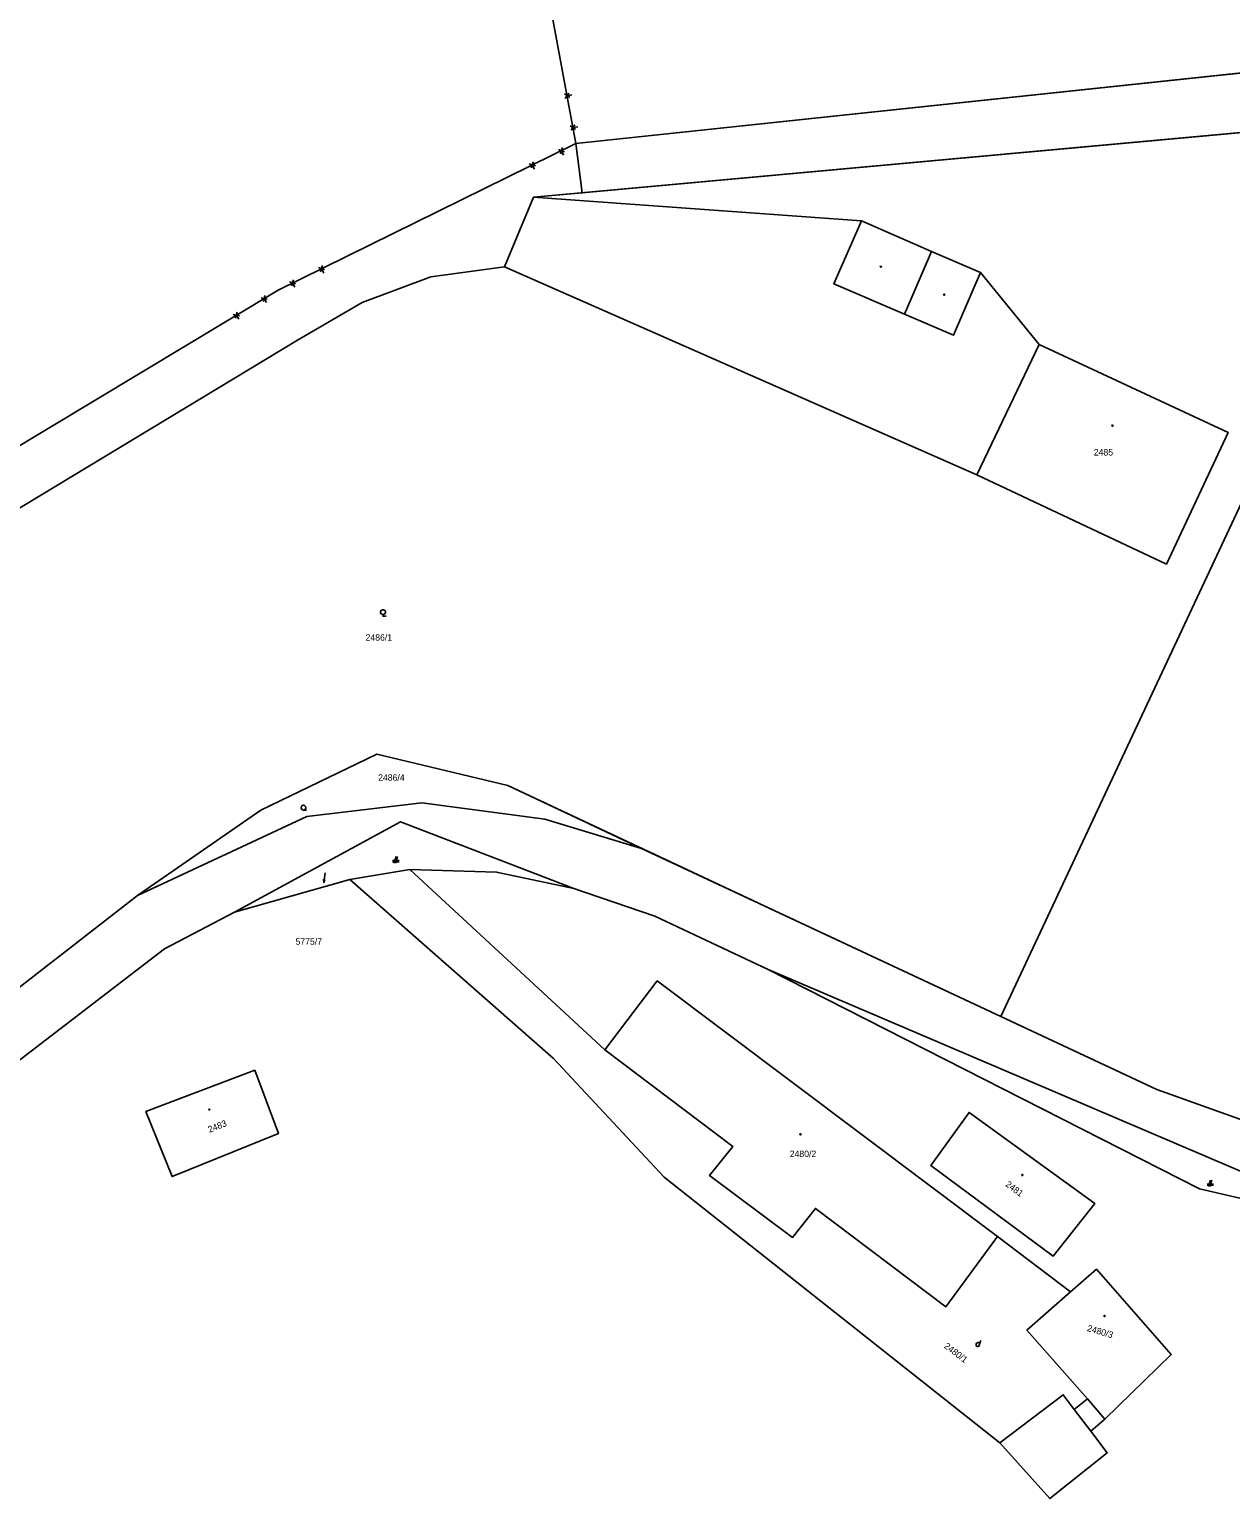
# Model space of a CAD drawing. Extents: x -439750 to -439180, y -1258684 to -1258308.
# Drawn here: x -439544.4 to -439470.2, y -1258447.6 to -1258356.9 of the extents above; entities that cross this region are included whole.
import ezdxf

# ---------------------------------------------------------------- set-up
doc = ezdxf.new("R2010")
doc.units = 0
doc.layers.add('KATASTER', color=7, linetype='Continuous')
doc.layers.add('UOV', color=7, linetype='Continuous')

# ---------------------------------------------------------------- blocks, each defined once
blk = doc.blocks.new('402')
blk.add_lwpolyline([(0.09, 0.15), (0.18, 0), (0.09, -0.15), (-0.09, -0.15), (-0.18, 0), (-0.09, 0.15), (0.09, 0.15)])
blk = doc.blocks.new('SIPKA_2')
blk.add_line((-0.2, 2), (0, 3))
blk.add_lwpolyline([(0, 0), (0, 3), (0.2, 2)])
blk = doc.blocks.new('CESTA')
for p, q in [((-0.32, 0.8), (-1, 0.8)), ((-1, 0.4), (-0.46, 0.4)), ((0.1, 2), (-0.6, 0)), ((-0.1, 0), (0.5, 2)), ((0.02, 0.4), (1, 0.4)), ((1, 0.8), (0.14, 0.8))]:
    blk.add_line(p, q)
blk = doc.blocks.new('DVUR')
blk.add_line((0.63, 0.99), (0.9, 1.89))
blk.add_lwpolyline([(0.45, 0), (0.45, 0.27), (0.63, 0.99), (0.54, 1.17), (0.36, 1.26), (0.09, 1.26), (-0.18, 1.17), (-0.36, 0.99), (-0.54, 0.72), (-0.54, 0.36), (-0.45, 0.09), (-0.27, 0), (0, 0), (0.18, 0.09), (0.45, 0.27)])
blk = doc.blocks.new('304')
blk.add_lwpolyline([(0, 0), (-0.38, 0.1), (-0.65, 0.37), (-0.75, 0.74), (-0.65, 1.11), (-0.38, 1.38), (-0.01, 1.48), (0.36, 1.38), (0.63, 1.11), (0.73, 0.73), (0.63, 0.35), (0.36, 0.08), (-0.02, -0.02), (0.98, -0.02)])
blk = doc.blocks.new('305')
blk.add_lwpolyline([(0, 0.53), (-0.19, 0.53), (-0.53, 0.72), (-0.72, 1.06), (-0.72, 1.45), (-0.53, 1.79), (-0.19, 1.98), (0.2, 1.98), (0.54, 1.79), (0.73, 1.45), (0.73, 1.06), (0.54, 0.72), (0.2, 0.53), (0.01, 0.53), (0.01, 0), (1.01, 0)])
blk = doc.blocks.new('2072')
for p, q in [((-4.3, 0.7), (-5.7, -0.7)), ((-5.7, 0.7), (-4.3, -0.7)), ((-5, 0), (-5, -1.5)), ((4.3, 0.7), (5.7, -0.7)), ((5.7, 0.7), (4.3, -0.7)), ((5, 0), (5, -1.5))]:
    blk.add_line(p, q)

msp = doc.modelspace()

# ---------------------------------------------------------------- linework, layer by layer
at = {"layer": 'KATASTER'}
for p, q in [((-439490.38, -1258374.47), (-439488.71, -1258370.59)), ((-439482.06, -1258376.34), (-439485.92, -1258384.39)), ((-439479.9, -1258442.07), (-439478.88, -1258443.41)), ((-439479.09, -1258441.42), (-439478, -1258442.67))]:
    msp.add_line(p, q, dxfattribs=at)
for points in [[(-439255.265, -1258349.384), (-439254.59, -1258356.61), (-439259.45, -1258374.06), (-439265.25, -1258367.53), (-439273.81, -1258367.89), (-439294.34, -1258362.99), (-439319.08, -1258361.05), (-439328.04, -1258358.53), (-439357.98, -1258347.42), (-439361.22, -1258351.62), (-439365.48, -1258348.34), (-439391.19, -1258328.53), (-439415.15, -1258317.05), (-439445.45, -1258309.53), (-439455.48, -1258307.79), (-439478.63, -1258311.39), (-439488.88, -1258312.99), (-439507.94, -1258320.79), (-439517.56, -1258326.72), (-439510.66, -1258363.93), (-439529.05, -1258372.98), (-439583.01, -1258405.44)], [(-439583.01, -1258405.44), (-439529.05, -1258372.98), (-439510.66, -1258363.93), (-439517.56, -1258326.72), (-439507.94, -1258320.79), (-439488.88, -1258312.99), (-439478.63, -1258311.39), (-439455.48, -1258307.79), (-439445.45, -1258309.53), (-439415.15, -1258317.05), (-439391.19, -1258328.53), (-439365.48, -1258348.34), (-439361.22, -1258351.62), (-439357.98, -1258347.42), (-439328.04, -1258358.53), (-439319.08, -1258361.05), (-439294.34, -1258362.99), (-439273.81, -1258367.89), (-439265.25, -1258367.53), (-439259.45, -1258374.06), (-439254.59, -1258356.61), (-439255.265, -1258349.384)], [(-439562.436, -1258308.807), (-439517.56, -1258326.72), (-439510.66, -1258363.93), (-439529.05, -1258372.98), (-439583.01, -1258405.44), (-439590.88, -1258409.26), (-439606.92, -1258408.85), (-439661.16, -1258372.28), (-439678.1, -1258360.24), (-439700.63, -1258331.393)], [(-439583.01, -1258405.44), (-439529.05, -1258372.98), (-439510.66, -1258363.93), (-439469.66, -1258359.58), (-439457.56, -1258358.3), (-439442.28, -1258360.05), (-439426.53, -1258366.38), (-439414.38, -1258373.64), (-439402.31, -1258380.87), (-439389.09, -1258387.3), (-439380.93, -1258392.19), (-439379.33, -1258392.51), (-439372.39, -1258393.61), (-439364.9, -1258394.3), (-439360.22, -1258395.64), (-439331.05, -1258396.01), (-439324.92, -1258395.23), (-439316.1, -1258393.08), (-439301.55, -1258387.38)], [(-439269.36, -1258377.15), (-439315.05, -1258395.8), (-439324.38, -1258397.9), (-439329.65, -1258398.85), (-439367.83, -1258398.64), (-439381.39, -1258394.16), (-439403.76, -1258383.09), (-439428.41, -1258368.76), (-439442.76, -1258364.07), (-439458.37, -1258362.23), (-439513.27, -1258367.25), (-439515.07, -1258371.54), (-439519.61, -1258372.16), (-439523.86, -1258373.74), (-439527.84, -1258376.06), (-439569.67, -1258401.31)], [(-439569.67, -1258401.31), (-439527.84, -1258376.06), (-439523.86, -1258373.74), (-439519.61, -1258372.16), (-439515.07, -1258371.54), (-439485.92, -1258384.39), (-439474.21, -1258389.89), (-439470.4, -1258381.78), (-439482.06, -1258376.34), (-439485.68, -1258371.89), (-439488.71, -1258370.59), (-439493.04, -1258368.7), (-439513.27, -1258367.25), (-439458.37, -1258362.23), (-439484.43, -1258417.81), (-439506.61, -1258407.45), (-439514.87, -1258403.56), (-439522.96, -1258401.62), (-439530.12, -1258405.09), (-439537.73, -1258410.35), (-439547.65, -1258418.05)], [(-439493.04, -1258368.7), (-439494.74, -1258372.59), (-439490.38, -1258374.47), (-439487.35, -1258375.77), (-439485.68, -1258371.89)], [(-439547.65, -1258418.05), (-439537.73, -1258410.35), (-439527.28, -1258405.47), (-439520.18, -1258404.63), (-439512.57, -1258405.64), (-439506.61, -1258407.45), (-439484.43, -1258417.81), (-439474.81, -1258422.32), (-439466.86, -1258425.16), (-439456.86, -1258427.2), (-439444.81, -1258427.42), (-439422.62, -1258423.93), (-439418.29, -1258423.4), (-439390.34, -1258418.93), (-439355.32, -1258412.49), (-439342.07, -1258411.63), (-439307.35, -1258399.88)], [(-439304.03, -1258403.29), (-439334.89, -1258413.69), (-439341.3, -1258415.85), (-439354.3, -1258417.7), (-439355.78, -1258417.92), (-439355.89, -1258417.18), (-439387.21, -1258424.13), (-439387, -1258423.44), (-439415.05, -1258427.42), (-439434.74, -1258431.72), (-439442.45, -1258432.5), (-439453.89, -1258431.74), (-439461.05, -1258431.03), (-439498.8, -1258414.92), (-439505.79, -1258411.63), (-439510.78, -1258409.92), (-439521.49, -1258405.8), (-439531.73, -1258411.37), (-439536.05, -1258413.64), (-439546.05, -1258421.31)], [(-439546.05, -1258421.31), (-439536.05, -1258413.64), (-439531.73, -1258411.37), (-439524.61, -1258409.37), (-439512.05, -1258420.41), (-439505.22, -1258427.74), (-439484.49, -1258444.14), (-439481.41, -1258447.58), (-439477.86, -1258444.75), (-439478.88, -1258443.41), (-439478, -1258442.67), (-439473.91, -1258438.68), (-439478.53, -1258433.42), (-439480.12, -1258434.81), (-439484.64, -1258431.41), (-439505.64, -1258415.62), (-439508.88, -1258419.88), (-439520.91, -1258408.75), (-439515.56, -1258408.91), (-439510.78, -1258409.92), (-439505.79, -1258411.63), (-439498.8, -1258414.92), (-439472.17, -1258428.45), (-439461.05, -1258431.03)]]:
    msp.add_lwpolyline(points, dxfattribs=at)
for points in [[(-439418.29, -1258423.4), (-439428.73, -1258408.86), (-439436.27, -1258398.27), (-439433.21, -1258391.81), (-439448.48, -1258384.63), (-439451.43, -1258391.1), (-439444.69, -1258394.29), (-439445.8, -1258396.64), (-439441.57, -1258398.64), (-439431.25, -1258409.67), (-439422.62, -1258423.93), (-439444.81, -1258427.42), (-439456.86, -1258427.2), (-439466.86, -1258425.16), (-439474.81, -1258422.32), (-439484.43, -1258417.81), (-439458.37, -1258362.23), (-439442.76, -1258364.07), (-439428.41, -1258368.76), (-439403.76, -1258383.09), (-439381.39, -1258394.16), (-439367.83, -1258398.64), (-439368.16, -1258411.35), (-439390.34, -1258418.93)], [(-439474.21, -1258389.89), (-439485.92, -1258384.39), (-439515.07, -1258371.54), (-439513.27, -1258367.25), (-439493.04, -1258368.7), (-439488.71, -1258370.59), (-439485.68, -1258371.89), (-439482.06, -1258376.34), (-439470.4, -1258381.78)], [(-439506.61, -1258407.45), (-439512.57, -1258405.64), (-439520.18, -1258404.63), (-439527.28, -1258405.47), (-439537.73, -1258410.35), (-439530.12, -1258405.09), (-439522.96, -1258401.62), (-439514.87, -1258403.56)], [(-439520.91, -1258408.75), (-439524.61, -1258409.37), (-439531.73, -1258411.37), (-439521.49, -1258405.8), (-439510.78, -1258409.92), (-439515.56, -1258408.91)], [(-439524.61, -1258409.37), (-439520.91, -1258408.75), (-439508.88, -1258419.88), (-439500.97, -1258425.85), (-439502.42, -1258427.63), (-439497.29, -1258431.46), (-439495.88, -1258429.67), (-439487.83, -1258435.74), (-439484.64, -1258431.41), (-439480.12, -1258434.81), (-439482.82, -1258437.18), (-439479.09, -1258441.42), (-439479.9, -1258442.07), (-439480.58, -1258441.17), (-439484.49, -1258444.14), (-439505.22, -1258427.74), (-439512.05, -1258420.41)], [(-439498.8, -1258414.92), (-439461.05, -1258431.03), (-439472.17, -1258428.45)], [(-439484.64, -1258431.41), (-439487.83, -1258435.74), (-439495.88, -1258429.67), (-439497.29, -1258431.46), (-439502.42, -1258427.63), (-439500.97, -1258425.85), (-439508.88, -1258419.88), (-439505.64, -1258415.62)], [(-439535.58, -1258427.7), (-439537.2, -1258423.68), (-439530.49, -1258421.14), (-439529.03, -1258425.05)], [(-439537.2, -1258423.68), (-439535.58, -1258427.7), (-439529.03, -1258425.05), (-439530.49, -1258421.14)], [(-439481.19, -1258432.61), (-439488.76, -1258427.01), (-439486.39, -1258423.74), (-439478.62, -1258429.37)], [(-439488.76, -1258427.01), (-439481.19, -1258432.61), (-439478.62, -1258429.37), (-439486.39, -1258423.74)], [(-439484.49, -1258444.14), (-439480.58, -1258441.17), (-439479.9, -1258442.07), (-439479.09, -1258441.42), (-439482.82, -1258437.18), (-439480.12, -1258434.81), (-439478.53, -1258433.42), (-439473.91, -1258438.68), (-439478, -1258442.67), (-439478.88, -1258443.41), (-439477.86, -1258444.75), (-439481.41, -1258447.58)]]:
    msp.add_lwpolyline(points, close=True, dxfattribs=at)
at = {"layer": 'UOV'}
for points in [[(-439301.55, -1258387.38), (-439316.1, -1258393.08), (-439324.92, -1258395.23), (-439331.05, -1258396.01), (-439360.22, -1258395.64), (-439364.9, -1258394.3), (-439367.7, -1258394.04), (-439372.39, -1258393.61), (-439378.2, -1258389.67), (-439379.33, -1258392.51), (-439380.93, -1258392.19), (-439389.09, -1258387.3), (-439402.31, -1258380.87), (-439414.38, -1258373.64), (-439426.53, -1258366.38), (-439442.28, -1258360.05), (-439457.56, -1258358.3), (-439510.66, -1258363.93), (-439529.05, -1258372.98), (-439583.01, -1258405.44)], [(-439547.65, -1258418.05), (-439537.73, -1258410.35), (-439530.12, -1258405.09), (-439522.96, -1258401.62), (-439514.87, -1258403.56), (-439499.09, -1258410.96), (-439484.43, -1258417.81), (-439474.81, -1258422.32), (-439466.86, -1258425.16), (-439456.86, -1258427.2), (-439444.81, -1258427.42), (-439422.62, -1258423.93), (-439422.26, -1258423.89), (-439421.18, -1258423.75), (-439418.29, -1258423.4), (-439390.34, -1258418.93)], [(-439387, -1258423.44), (-439415.05, -1258427.42), (-439434.74, -1258431.72), (-439442.45, -1258432.5), (-439453.89, -1258431.74), (-439461.05, -1258431.03), (-439498.8, -1258414.92), (-439505.79, -1258411.63), (-439510.78, -1258409.92), (-439521.49, -1258405.8), (-439531.73, -1258411.37), (-439536.05, -1258413.64), (-439546.05, -1258421.31)]]:
    msp.add_lwpolyline(points, dxfattribs=at)
for points in [[(-439510.66, -1258363.93), (-439457.56, -1258358.3), (-439442.28, -1258360.05), (-439426.53, -1258366.38), (-439414.38, -1258373.64), (-439402.31, -1258380.87), (-439389.09, -1258387.3), (-439380.93, -1258392.19), (-439379.33, -1258392.51), (-439372.39, -1258393.61), (-439367.7, -1258394.04), (-439367.83, -1258398.64), (-439381.39, -1258394.16), (-439403.76, -1258383.09), (-439428.41, -1258368.76), (-439442.76, -1258364.07), (-439458.37, -1258362.23), (-439472.18, -1258363.49), (-439510.27, -1258366.98)], [(-439583.01, -1258405.44), (-439529.05, -1258372.98), (-439510.66, -1258363.93), (-439510.27, -1258366.98), (-439513.27, -1258367.25), (-439515.07, -1258371.54), (-439519.61, -1258372.16), (-439523.86, -1258373.74), (-439527.84, -1258376.06), (-439569.67, -1258401.31), (-439578.76, -1258414.74), (-439581.78, -1258408.62)]]:
    msp.add_lwpolyline(points, close=True, dxfattribs=at)

# ---------------------------------------------------------------- block references
at = {"layer": 'KATASTER'}
for name, p, xscale, yscale, rotation in [('2072', (-439511.025, -1258361.964), 0.19999999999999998, 0.20000000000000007, 100.49679699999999), ('2072', (-439512.454, -1258364.813), 0.2, 0.20000000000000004, 26.184170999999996), ('2072', (-439527.256, -1258372.097), 0.2, 0.20000000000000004, 26.184170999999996), ('2072', (-439530.764, -1258374.011), 0.2, 0.20000000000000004, 31.054311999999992), ('SIPKA_2', (-439526.13, -1258408.96), 0.2, 0.20000000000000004, 170.283057)]:
    msp.add_blockref(name, p, dxfattribs=dict(at, xscale=xscale, yscale=yscale, rotation=rotation))
at = {"layer": 'KATASTER', "xscale": 0.2, "yscale": 0.20000000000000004}
for name, p in [('402', (-439491.84, -1258371.54)), ('402', (-439487.93, -1258373.26)), ('402', (-439477.54, -1258381.34)), ('305', (-439522.57, -1258393.11)), ('304', (-439527.48, -1258405.08)), ('CESTA', (-439521.78, -1258408.35)), ('402', (-439533.29, -1258423.56)), ('402', (-439496.8, -1258425.09)), ('402', (-439483.1, -1258427.61)), ('CESTA', (-439471.5, -1258428.32)), ('402', (-439478.03, -1258436.31)), ('DVUR', (-439485.85, -1258438.19))]:
    msp.add_blockref(name, p, dxfattribs=at)

# ---------------------------------------------------------------- texts
at = {"layer": 'KATASTER'}
for s, p in [('2485', (-439478.692, -1258383.19)), ('2486/1', (-439523.645, -1258394.62)), ('2486/4', (-439522.871, -1258403.27)), ('5775/7', (-439527.972, -1258413.39)), ('2480/2', (-439497.462, -1258426.5))]:
    msp.add_text(s, height=0.4, dxfattribs=at).set_placement(p)
for s, rotation, p in [('2483', 21.486, (-439533.282, -1258425.001)), ('2481', 323.034, (-439484.184, -1258428.256)), ('2480/3', 343.603, (-439479.138, -1258437.226)), ('2480/1', 322.633, (-439487.971, -1258438.237))]:
    msp.add_text(s, height=0.4, rotation=rotation, dxfattribs=at).set_placement(p)

doc.saveas('drawing.dxf')
